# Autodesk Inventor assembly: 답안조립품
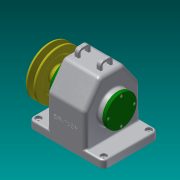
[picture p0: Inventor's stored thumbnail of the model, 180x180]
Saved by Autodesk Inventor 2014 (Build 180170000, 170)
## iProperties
Created: 2016-12
Part Number: 답안조립품
Document SubType Name: Assembly
Designer: net
Author: net
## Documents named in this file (15)
- C:\Users\net\Desktop\461207V1009\답안조립품.iam
- C:\Users\net\Desktop\461207V1009\본체.ipt
- C:\Users\net\Desktop\461207V1009\V-벨트풀리.ipt
- C:\Users\net\Desktop\461207V1009\뒤커버.ipt
- C:\Users\net\Desktop\461207V1009\멈춤나사 - M4x10.ipt
- C:\Users\net\Desktop\461207V1009\베어링 6203.ipt
- C:\Users\net\Desktop\461207V1009\볼트 M3 x 8.ipt
- C:\Users\net\Desktop\461207V1009\볼트 M3 x 10.ipt
- C:\Users\net\Desktop\461207V1009\부시.ipt
- C:\Users\net\Desktop\461207V1009\스퍼기어.ipt
- C:\Users\net\Desktop\461207V1009\앞커버.ipt
- C:\Users\net\Desktop\461207V1009\오일씰 28 40 8.ipt
- C:\Users\net\Desktop\461207V1009\축.ipt
- C:\Users\net\Desktop\461207V1009\키 - 5 x 5 x 18.ipt
- C:\Users\net\Desktop\461207V1009\키 - 6 x 6 x 22.ipt
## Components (9 placed, 3 different names)
1. V-벨트풀리:1
2. ISO 4762 M3 x 8:1
3. ISO 4762 M3 x 8:2
4. ISO 4762 M3 x 8:3
5. ISO 4762 M3 x 8:4
6. ISO 4762 M3 x 10:1
7. ISO 4762 M3 x 10:2
8. ISO 4762 M3 x 10:3
9. ISO 4762 M3 x 10:4
